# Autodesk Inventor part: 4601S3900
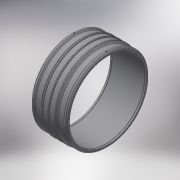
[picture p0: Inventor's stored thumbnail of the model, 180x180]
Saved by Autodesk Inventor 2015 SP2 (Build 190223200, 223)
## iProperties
Created: 2017-06
Part Number: 4601S3900
Material: Generic
Description: PLASSON SUPER LIGHTFIT 900 MM
Document SubType Name: Modeling
Designer: KIM
Mass: 36000.5 g
Surface Area: 27945.3 cm^2
Volume: 36000.5 cm^3
Density: 1 g/cm^3
Appearance: Default
Author: KIM
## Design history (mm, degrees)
derived "4601S3.ipt"
feature "Solid1::4601S3.ipt"
tag "TaggingFeature1"
body "Solid1"
other parameters: "d14" = 17.6296, "d19" = 3.52592, "d20" = 168 deg, "d23" = 983, "d24" = 940.9, "d25" = 135 deg, "d26" = 168, "d27" = 135 deg, "d29" = 485, "d35" = 15, "d39" = 0, "d40" = 4, "d41" = 14, "d42" = 0, "d43" = 135 deg, "d44" = 46.2, "d45" = 16.8, "d46" = 16.8, "d47" = 16.8, "d48" = 963.34, "d49" = 983, "d50" = 4.915, "d51" = 6, "d52" = 0, "D_" = 983, "A_" = 485, "d_2" = 12
